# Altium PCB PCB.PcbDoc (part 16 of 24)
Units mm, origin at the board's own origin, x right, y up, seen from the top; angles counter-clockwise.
Board outline 100 x 160 mm, 10 copper layers (TOP_L1, L2, L3, L4, L5, L6, L7, L8, L9, BOTTOM_L10), stack 1.946 mm thick; 1358 components, 1149 nets, 6777 pads, 10914 vias.
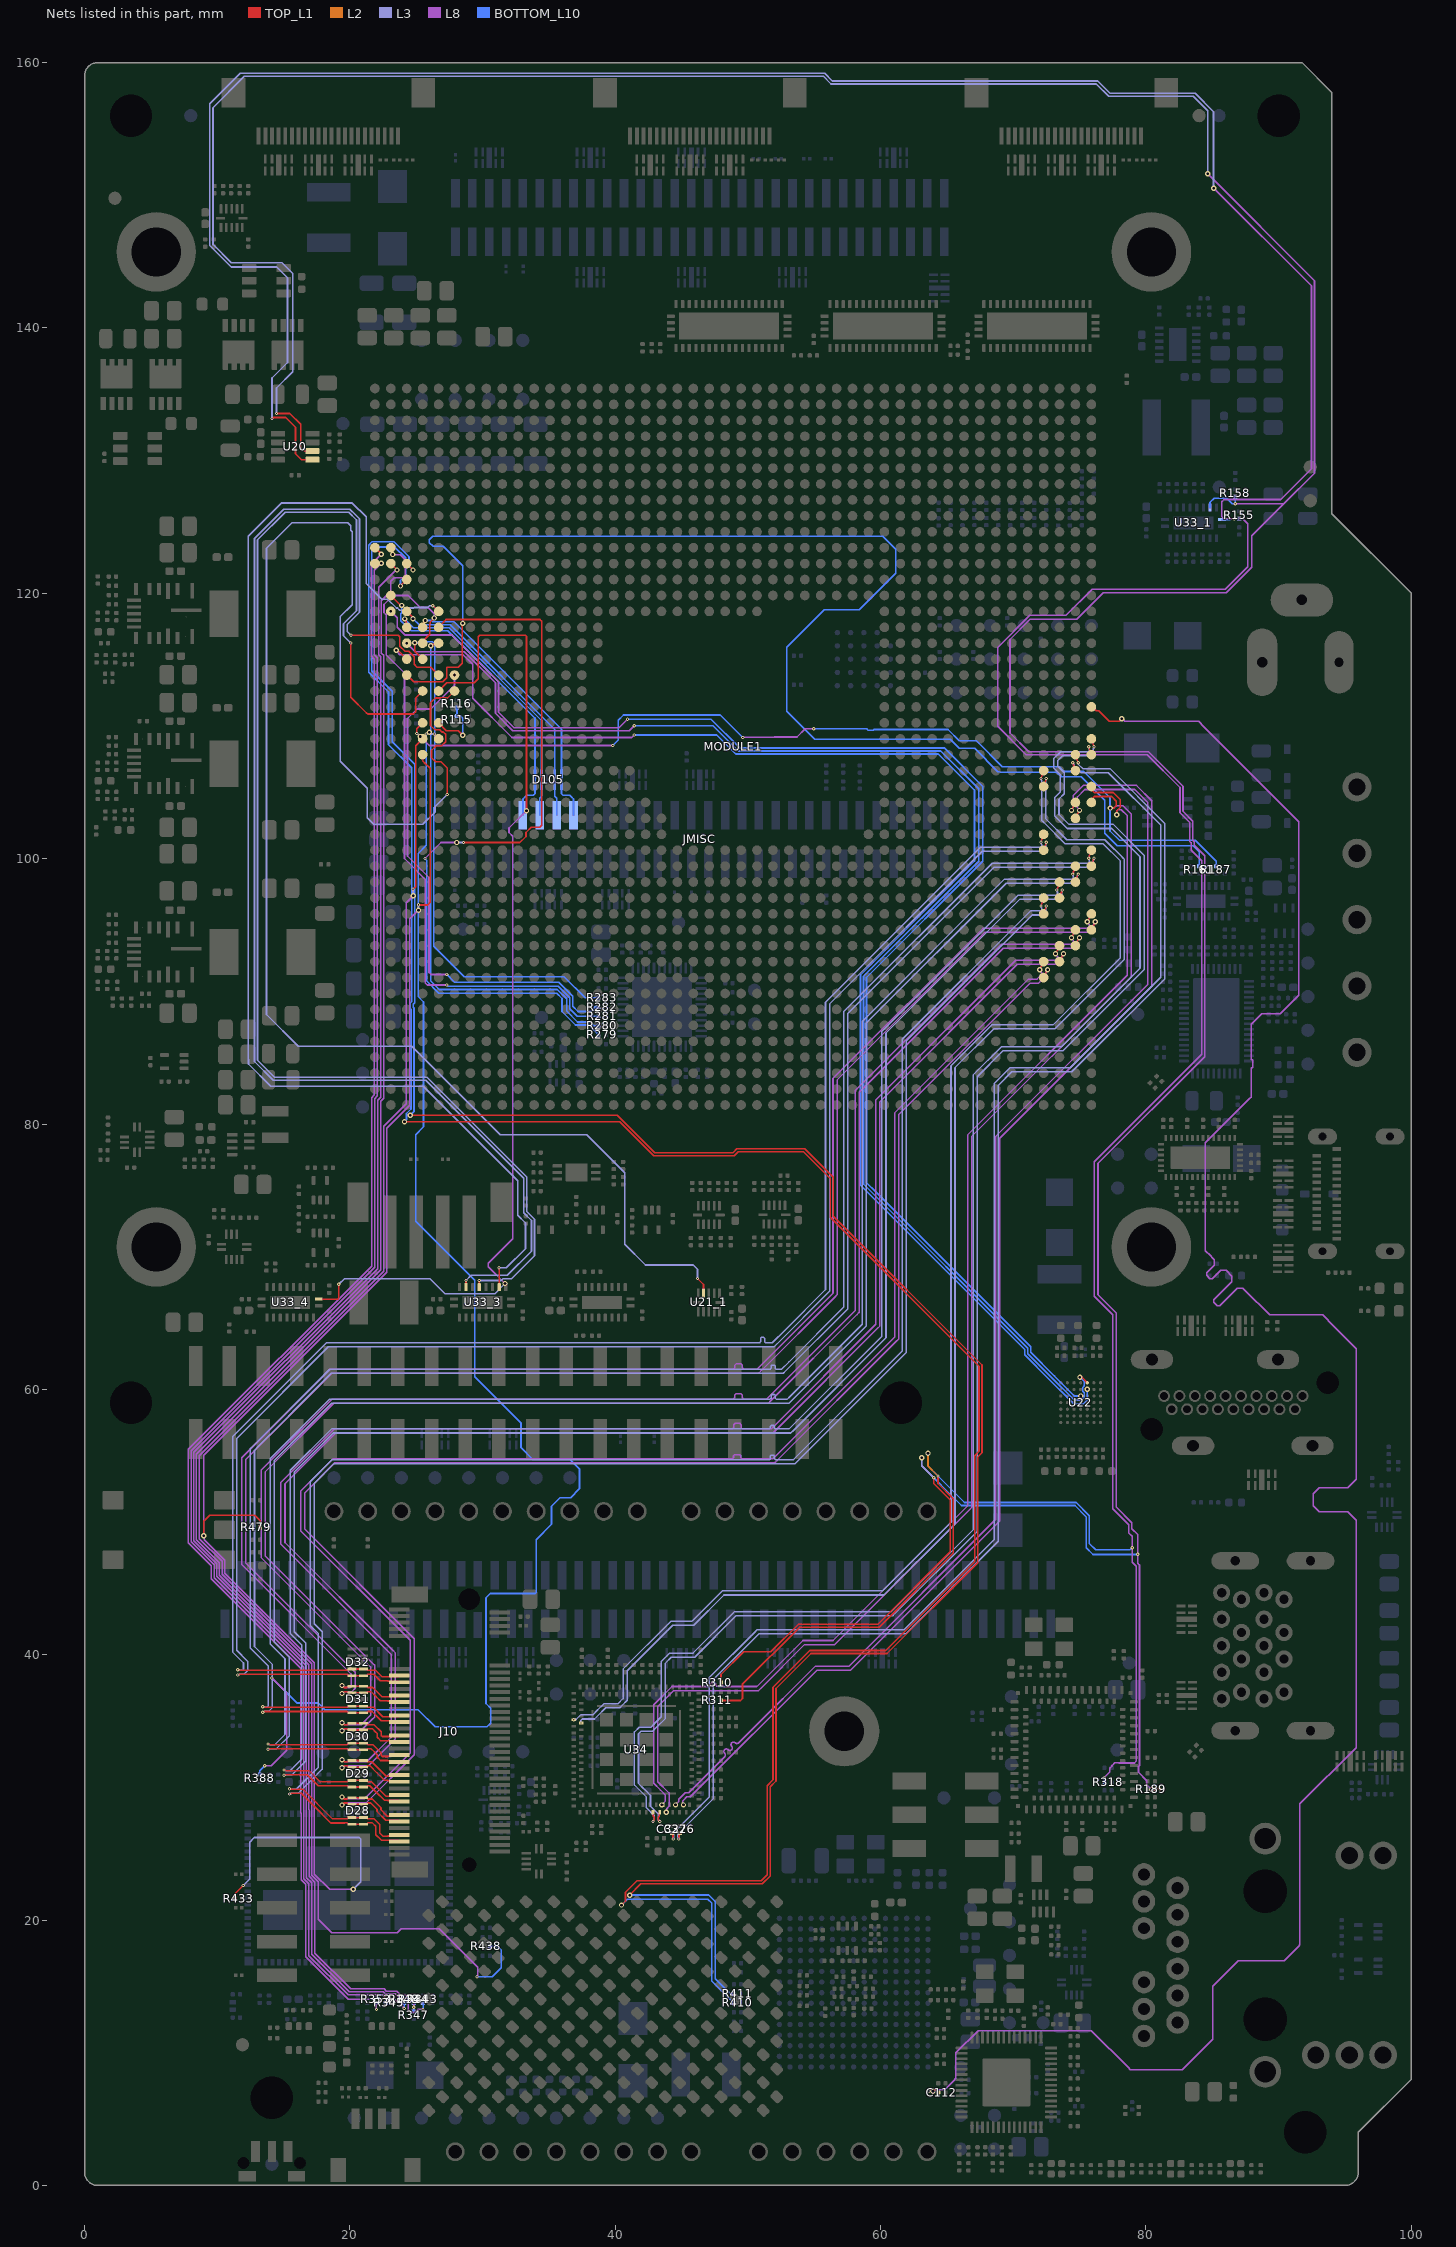
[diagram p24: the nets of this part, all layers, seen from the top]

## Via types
v1: diameter 0.25, hole 0.1, TOP_L1 to L2, tented both sides, 3439 vias
v2: diameter 0.25, hole 0.1, L2 to L3, tented both sides, 2256 vias
v3: diameter 0.25, hole 0.1, L9 to BOTTOM_L10, tented both sides, 1685 vias
v4: diameter 0.25, hole 0.1, L8 to L9, tented both sides, 1675 vias
v5: diameter 0.4, hole 0.2, L3 to L8, tented both sides, 1251 vias
v6: diameter 0.6, hole 0.3, TOP_L1 to BOTTOM_L10, tented both sides, 600 vias
v7: diameter 0.24, hole 0.1, TOP_L1 to L2, tented both sides, 8 vias

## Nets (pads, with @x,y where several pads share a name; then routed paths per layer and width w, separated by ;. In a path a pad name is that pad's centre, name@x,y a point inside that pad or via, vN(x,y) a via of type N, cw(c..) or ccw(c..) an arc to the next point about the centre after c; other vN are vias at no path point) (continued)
MD_GPIO_94_1: MODULE1.C28 R161.1 | length 107.1
  TOP_L1 w0.1: MODULE1.C28@24.282,113.836 24.797,113.321 26.895,113.321 26.909,113.335 26.982,113.335 27.282,113.635 27.282,114.376 27.341,114.435 28.182,114.435 28.482,114.735 28.482,117.702 v5(28.509,117.729)
  BOTTOM_L10 w0.1: v5(28.509,117.729) 28.509,122.074 27.048,123.535 26.261,123.535 25.982,123.814 25.982,124.029 26.26,124.306 60.177,124.306 61.149,123.335 61.149,121.516 58.401,118.768 55.749,118.768 52.914,115.933 52.914,111.109 55.037,108.986 65.237,108.986 65.915,108.308 67.082,108.308 68.83,106.561 68.954,106.561 69.004,106.511 73.29,106.511 73.643,106.158 75.136,106.158 76.876,104.418 76.876,101.918 77.829,100.965 83.547,100.965 84.003,100.509 R161.1@84.003,99.424
  other v1: 28.509,117.729
  other v2: 28.509,117.729
  other v3: 28.509,117.729
  other v4: 28.509,117.729
MD_GPIO_95_1: MODULE1.C35 R410.2 | length 179.3
  TOP_L1 w0.127: v4(24.113,80.163) 40.337,80.163 42.886,77.613 48.965,77.613 49.255,77.904 54.19,77.904 56.204,75.89 56.204,73.166 56.204,72.959 67.416,61.747 67.416,55.325 67.088,54.998 67.088,47.028 60.378,40.318 54.658,40.318 51.884,37.544 51.884,30.571 51.448,30.135 51.448,23.416 50.989,22.956 41.637,22.956 40.768,22.087 40.768,21.433 v5(40.463,21.129) ; MODULE1.C35@24.282,122.236 24.75,121.768 v1(24.75,121.75)
  BOTTOM_L10 w0.127: v4(24.113,80.163) 24.113,80.177 24.265,80.329 24.265,80.787 24.608,81.13 24.608,88.638 24.546,88.7 24.546,89.127 24.655,89.235 24.655,106.853 22.912,108.596 22.912,112.563 21.42,114.055 21.42,123.631 21.664,123.875 23.316,123.875 24.446,122.744 24.446,122.054 v1(24.75,121.75) ; v5(40.463,21.129) 40.907,21.572 46.973,21.572 47.258,21.287 47.258,15.41 R410.2@48.92,13.749
  other v1: 40.463,21.129 24.113,80.163
  other v2: 40.463,21.129 24.113,80.163 24.75,121.75
  other v3: 40.463,21.129 24.113,80.163 24.75,121.75
  other v4: 40.463,21.129 24.75,121.75
  other v5: 24.113,80.163 24.75,121.75
MD_GPIO_96_1: MODULE1.C34 R411.2 | length 176.9
  TOP_L1 w0.127: v5(23.814,120.55) 23.814,120.568 MODULE1.C34@24.282,121.036 ; v1(24.554,80.667) 40.153,80.667 42.98,77.84 48.871,77.84 49.161,78.131 54.284,78.131 56.431,75.984 56.431,73.26 56.431,73.053 67.643,61.841 67.643,55.231 67.315,54.904 67.315,46.93 60.476,40.091 54.752,40.091 52.111,37.45 52.111,30.477 51.675,30.041 51.675,23.322 51.083,22.729 41.925,22.729 41.089,21.894 v3(41.089,21.875)
  BOTTOM_L10 w0.127: v5(23.814,120.55) 23.814,120.968 24.202,121.356 24.202,122.667 23.387,123.482 21.828,123.482 21.647,123.301 21.647,114.149 23.185,112.611 23.185,108.823 24.882,107.126 24.882,89.141 24.773,89.033 24.773,88.794 24.835,88.732 24.835,80.949 v1(24.554,80.667) ; v3(41.089,21.875) 41.099,21.884 47.046,21.884 47.53,21.399 47.53,15.572 48.654,14.449 R411.2@48.891,14.449
  other v1: 41.089,21.875 23.814,120.55
  other v2: 41.089,21.875 24.554,80.667 23.814,120.55
  other v3: 24.554,80.667 23.814,120.55
  other v4: 41.089,21.875 24.554,80.667 23.814,120.55
  other v5: 41.089,21.875 24.554,80.667
MD_GPIO_99_2: MODULE1.E25 R115.2 R116.2 | length 4.7
  TOP_L1 w0.127: MODULE1.E25@26.682,110.236 26.682,110.219 27.252,109.649 28.158,109.649 v4(28.503,109.304)
  BOTTOM_L10 w0.127: R116.2@28.069,111.399 R115.2@28.069,110.749 28.346,110.749 28.503,110.592 v4(28.503,109.304)
  other v1: 28.503,109.304
  other v2: 28.503,109.304
  other v3: 28.503,109.304
  other v5: 28.503,109.304
MD_GPIO_100_1: MODULE1.E24 R388.1 | length 115.8
  TOP_L1 w0.127: v2(26.348,109.398) 26.348,109.37 MODULE1.E24@26.682,109.036
  L3 w0.127: v5(25.99,109.516) 26.108,109.398 v2(26.348,109.398)
  L8 w0.1: v4(13.575,31.625) 14.084,31.625 15.252,32.792 15.252,37.115 v4(14.117,38.249)
  L8 w0.127: v4(25.754,109.4) 25.9,109.547 25.959,109.547 v5(25.99,109.516)
  BOTTOM_L10 w0.1: R388.1@13.2,30.96 13.2,31.25 v4(13.575,31.625)
  BOTTOM_L10 w0.127: v4(14.117,38.249) 16,36.367 17.591,36.367 18.109,35.849 25.135,35.849 26.425,34.559 30.331,34.559 30.616,34.844 30.616,35.959 30.25,36.325 30.25,44.287 30.58,44.616 33.976,44.616 34.05,44.691 34.05,48.676 35.196,49.821 35.196,51.197 35.834,51.835 36.631,51.835 37.296,52.5 37.296,54.006 36.601,54.7 33.8,54.7 32.9,55.6 32.9,57.449 29.4,60.949 29.4,68.223 24.95,72.673 24.95,79.2 25.55,79.8 25.55,89.2 25.14,89.61 25.14,100.39 25.754,101.004 v4(25.754,109.4)
  other v1: 26.348,109.398
  other v3: 13.575,31.625 14.117,38.249 25.754,109.4
MD_GPIO_101_1: MODULE1.D24 R438.1 | length 118.6
  TOP_L1 w0.127: v2(24.752,97.689) 24.954,97.89 24.954,108.508 MODULE1.D24@25.482,109.036
  L3 w0.127: v2(24.752,97.689) 24.757,97.684 24.757,97.218 v5(24.762,97.213)
  L8 w0.1: v5(24.762,97.213) 24.233,96.685 24.233,81.533 22.541,79.841 22.541,68.915 8.631,55.005 8.631,48.756 10.359,47.028 10.359,46.063 17.105,39.317 17.105,28.414 17.124,28.395 17.124,23.373 17.596,22.901 17.596,20.079 18.622,19.053 23.56,19.053 23.854,19.348 26.729,19.348 29.635,16.443 29.635,15.796 v3(29.573,15.734)
  BOTTOM_L10 w0.127: v3(29.573,15.734) 30.724,15.734 31.4,16.41 31.4,17.749 31.139,18.01 R438.1@30.55,18.01
  other v1: 24.752,97.689
  other v4: 29.573,15.734
MD_GPIO_103_1: MODULE1.D23 R433.2 R479.2 | length 122.4
  TOP_L1 w0.127: v1(8.981,48.962) 8.981,50.048 9.436,50.503 12.832,50.503 13.232,50.103 R479.2@13.232,49.597 ; R433.2@11.335,21.621 11.333,21.623 11.333,21.981 v1(11.958,22.607) ; v2(25.162,96.513) 25.167,96.508 25.856,96.508 26.062,96.713 26.062,106.804 25.701,107.165 25.681,107.165 25.482,107.364 MODULE1.D23@25.482,107.836
  L3 w0.127: v1(11.958,22.607) 12.45,23.099 12.45,25.875 12.795,26.22 20.698,26.22 20.81,26.108 20.81,22.877 v5(20.252,22.319) ; v5(25.162,96.113) v2(25.162,96.513)
  L8 w0.1: v1(8.981,48.962) 9.008,48.935 9.008,48.662 10.559,47.111 10.559,46.146 17.313,39.392 17.313,28.489 17.324,28.478 17.324,23.456 18.46,22.319 v5(20.252,22.319) ; v5@8.981,49.001 8.981,55.034 22.768,68.821 22.768,79.678 24.516,81.426 24.516,95.467 v5(25.162,96.113)
  other v1: 25.162,96.513
  other v2: 11.958,22.607 8.981,48.962
  other v5: 8.981,48.962
MD_GPIO_104_1: MODULE1.D25 R187.1 | length 70.4
  TOP_L1 w0.127: v2(25.04,109.427) 25.04,109.794 MODULE1.D25@25.482,110.236
  L3 w0.127: v2(25.04,109.427) 25.056,109.427 25.281,109.202 v5(25.298,109.202)
  L8 w0.127: v5(25.298,109.202) 25.97,108.529 v4(39.809,108.529) ; v4(49.609,109.129) 49.618,109.138 51.953,109.138 51.986,109.171 53.698,109.171 54.307,109.78 v4(54.961,109.78)
  BOTTOM_L10 w0.127: v4(39.809,108.529) 40.227,108.947 40.227,110.435 40.621,110.829 47.909,110.829 v4(49.609,109.129) ; v4(54.961,109.78) 58.943,109.78 59.05,109.673 59.434,109.673 59.491,109.729 65.078,109.729 65.932,108.876 67.224,108.876 69.175,106.925 73.461,106.925 73.815,106.571 75.308,106.571 77.29,104.59 77.29,102.09 78.001,101.378 83.718,101.378 85.303,99.793 R187.1@85.303,99.424
  other v1: 25.04,109.427
  other v3: 39.809,108.529 49.609,109.129 54.961,109.78
MD_GPIO_105_1: MODULE1.E28 U33_3.8 | length 102.5
  TOP_L1 w0.127: v1(20.082,116.836) 23.642,116.836 23.754,116.724 23.754,116.017 24.15,115.621 24.445,115.621 24.841,115.225 24.841,114.652 25.056,114.436 26.082,114.436 MODULE1.E28@26.682,113.836 ; U33_3.8@28.75,67.7 v1(28.75,68.208)
  L3 w0.127: v1(20.082,116.836) 19.794,117.125 19.794,117.652 20.457,118.316 20.72,118.579 20.72,125.617 20.457,125.88 19.993,126.345 19.31,126.345 15.022,126.345 12.8,124.122 12.8,86.871 12.8,86.292 12.8,85.685 12.8,85.051 12.805,85.047 12.805,84.714 14.217,83.302 25.709,83.302 33.105,75.907 33.105,73.306 33.684,72.727 33.684,70.421 31.861,68.599 29.141,68.599 v1(28.75,68.208)
  other v2: 28.75,68.208 20.082,116.836
MD_GPIO_106_1: MODULE1.D27 U33_3.6 | length 104.6
  TOP_L1 w0.127: v2(20.069,116.249) 20.069,112.168 21.254,110.983 21.271,110.983 21.347,110.908 24.797,110.908 24.954,111.065 24.954,112.108 MODULE1.D27@25.482,112.636 ; U33_3.6@29.75,67.7 v2(29.75,68.208)
  L3 w0.127: v2(20.069,116.249) 19.52,116.798 19.52,117.699 20.493,118.673 20.493,125.523 19.899,126.118 15.117,126.118 13.027,124.028 13.027,85.145 13.032,85.141 13.032,84.808 14.311,83.529 25.803,83.529 33.332,76.001 33.332,73.4 33.911,72.821 33.911,70.069 32.18,68.339 31.54,68.339 31.409,68.208 v2(29.75,68.208)
  other v1: 29.75,68.208 20.069,116.249
MD_GPIO_107_1: MODULE1.E32 U33_3.3 | length 95.1
  TOP_L1 w0.127: v2(26.25,119.05) 26.259,119.05 26.673,118.636 MODULE1.E32@26.682,118.636 ; v2(31.241,69.17) 31.246,69.165 31.246,67.704 U33_3.3@31.25,67.7
  L3 w0.127: v2(26.25,119.05) 25.991,119.05 25.867,118.925 24.858,118.925 24.82,118.887 24.215,118.887 24.051,118.723 23.75,118.723 23.586,118.887 23.505,118.887 22.83,119.561 22.398,119.561 21.219,120.74 21.219,125.76 20.181,126.799 14.834,126.799 12.346,124.311 12.346,86.649 12.346,86.104 12.346,85.497 12.346,84.863 12.351,84.858 12.351,84.526 14.029,82.848 25.521,82.848 32.651,75.718 32.651,73.118 33.23,72.539 33.23,70.609 31.781,69.161 31.25,69.161 v2(31.241,69.17)
  other v1: 31.241,69.17 26.25,119.05
MD_GPIO_108_1: MODULE1.F27 U21_1.4 | length 129.9
  TOP_L1 w0.127: v2(27.34,104.84) 27.34,106.833 26.866,107.308 26.463,107.308 26.154,107.617 26.154,108.154 26.508,108.508 26.901,108.508 27.211,108.817 27.211,109.369 27.04,109.54 26.926,109.54 26.758,109.708 26.41,109.708 26.078,110.04 26.078,111.741 26.288,111.952 26.444,112.108 27.354,112.108 MODULE1.F27@27.882,112.636 ; v2(46.202,68.356) 46.65,67.908 U21_1.4@46.65,67.25
  L3 w0.127: v2(27.34,104.84) 26.406,103.906 26.406,103.497 25.495,102.586 21.789,102.586 21.302,103.073 21.302,105.301 19.269,107.334 19.269,118.249 20.169,119.149 20.169,124.649 20.056,124.763 20.056,125.084 19.829,125.31 15.635,125.31 13.708,123.383 13.708,88.258 16.102,85.865 24.652,85.865 31.331,79.185 37.855,79.185 38.105,78.936 40.71,76.331 40.71,70.943 42.278,69.374 45.884,69.374 46.202,69.056 v2(46.202,68.356)
  other v1: 46.202,68.356 27.34,104.84
MD_GPIO_109_1: MODULE1.E27 U33_4.1 | length 77.1
  TOP_L1 w0.127: U33_4.1@17.65,66.8 19.075,66.8 19.162,66.887 v1(19.162,67.913) ; MODULE1.E27@26.682,112.636 27.295,113.249 29.369,113.249 29.669,113.549 29.669,116.734 29.781,116.846 33.212,116.846 33.302,116.756 v5(33.302,103.621)
  L3 w0.127: v1(19.162,67.913) 19.592,68.343 26.032,68.343 27.162,67.213 30.929,67.213 v5(31.691,67.975)
  L8 w0.127: v5(31.691,67.975) 30.434,69.231 30.434,69.5 32.276,71.341 32.276,101.677 31.987,101.966 31.987,102.306 v5(33.302,103.621)
  other v1: 33.302,103.621
  other v2: 19.162,67.913 33.302,103.621
MD_LPASS_GPIO_110: MODULE1.F28 R282.1 | length 39.8
  L8 w0.127: v4(27.286,91.275) 26.113,91.275 25.964,91.424 25.964,98.574 24.334,100.204 24.334,110.561 25.052,111.279 26.09,111.279 27.882,113.07 v2(27.882,113.836)
  BOTTOM_L10 w0.127: v4(27.286,91.275) 27.886,90.675 35.732,90.675 36.786,89.62 36.786,88.875 37.186,88.475 38.186,88.475 38.428,88.716 38.428,88.816 R282.1@38.748,88.816
  other v1: 27.882,113.836
  other v3: 27.286,91.275
  other v4: 27.882,113.836
  other v5: 27.882,113.836
MD_LPASS_GPIO_111: MODULE1.D30 R281.1 | length 51.6
  TOP_L1 w0.127: MODULE1.D30@25.482,116.236 25.482,116.395 26.011,116.923 26.011,117.69 26.053,117.733 26.053,117.837 v5(26.359,118.142)
  L8 w0.127: v5(26.359,118.142) 26.359,118.454 25.877,118.935 25.284,118.935 24.385,119.835 23.255,119.835 22.571,119.151 22.571,118.549 22.743,118.377 22.743,116.98 22.743,116.257 22.743,115.351 24.107,113.987 24.107,100.005 25.683,98.43 25.683,90.624 25.831,90.475 v4(27.286,90.475)
  BOTTOM_L10 w0.127: v4(27.286,90.475) 27.386,90.375 35.711,90.375 36.559,89.526 36.559,88.684 37.127,88.116 R281.1@38.748,88.116
  other v1: 26.359,118.142
  other v2: 26.359,118.142
  other v3: 27.286,90.475
MD_LPASS_GPIO_112: MODULE1.E30 R280.1 | length 40.5
  TOP_L1 w0.127: v1(26.102,116.054) 26.135,116.054 26.217,116.136 26.582,116.136 MODULE1.E30@26.682,116.236
  BOTTOM_L10 w0.127: 26.101,114.404 26.101,90.78 26.743,90.138 35.626,90.138 36.332,89.432 36.332,88.511 37.157,87.687 38.098,87.687 38.369,87.416 R280.1@38.748,87.416 ; 26.102,114.405 v1(26.102,116.054)
  other v2: 26.102,116.054
  other v3: 26.102,116.054
  other v4: 26.102,116.054
  other v5: 26.102,116.054
MD_LPASS_GPIO_113: MODULE1.E31 R279.1 | length 58
  TOP_L1 w0.127: MODULE1.E31@26.682,117.436 27.04,117.794 27.04,117.814 27.244,118.018 34.323,118.018 34.452,117.888 34.452,102.513 34.303,102.365 33.663,102.365 33.265,101.966 33.265,101.671 32.807,101.213 v2(28.562,101.213)
  L3 w0.127: v5(28.062,101.213) v2(28.562,101.213)
  L8 w0.127: v3(25.662,100.013) 26.862,101.213 v5(28.062,101.213)
  BOTTOM_L10 w0.127: v3(25.662,100.013) 25.662,99.98 25.782,99.86 25.782,90.779 26.696,89.864 35.58,89.864 35.987,89.457 35.987,88.478 37.005,87.46 38.004,87.46 R279.1@38.748,86.716
  other v1: 28.562,101.213
  other v4: 25.662,100.013
MD_LPASS_GPIO_115: MODULE1.D29 R283.1 | length 39.9
  TOP_L1 w0.127: v2(24.894,116.281) 24.894,115.624 MODULE1.D29@25.482,115.036
  BOTTOM_L10 w0.127: v2(24.894,116.281) 25.575,116.281 25.637,116.342 26.221,116.342 26.39,116.173 26.39,103.894 26.328,103.832 26.328,93.388 28.609,91.107 36.139,91.107 37.73,89.516 R283.1@38.748,89.516
  other v1: 24.894,116.281
  other v3: 24.894,116.281
  other v4: 24.894,116.281
  other v5: 24.894,116.281
MD_LPASS_GPIO_120: D105.1 D105.10 JMISC.46 MODULE1.D31 | length 21.4
  TOP_L1 w0.127: MODULE1.D31@25.482,117.436 25.597,117.551 25.597,117.827 25.682,117.912 v1(25.682,117.945)
  BOTTOM_L10 w0.127: v1(25.682,117.945) 26.148,117.945 26.243,117.85 27.849,117.85 35.944,109.755 35.944,104.898 36.064,104.778 36.564,104.778 36.727,104.615 36.732,104.615 36.849,104.498 JMISC.46@36.849,103.278
  other v2: 25.682,117.945
  other v3: 25.682,117.945
  other v4: 25.682,117.945
  other v5: 25.682,117.945
MD_LPASS_GPIO_121: D105.2 D105.9 JMISC.48 MODULE1.C32 | length 21.4
  TOP_L1 w0.127: MODULE1.C32@24.282,118.636 24.726,118.192 24.726,118.109 v1(24.75,118.085)
  BOTTOM_L10 w0.127: v1(24.75,118.085) 25.212,117.623 27.557,117.623 35.444,109.736 D105.9@35.444,106.391 D105.2@35.444,105.516 35.444,104.698 35.579,104.563 JMISC.48@35.579,103.278
  other v2: 24.75,118.085
  other v3: 24.75,118.085
  other v4: 24.75,118.085
  other v5: 24.75,118.085
MD_LPASS_GPIO_122: D105.4 D105.7 JMISC.50 MODULE1.C31 | length 21.4
  TOP_L1 w0.127: v1(24.122,118.068) 24.122,118.035 24.256,117.901 24.256,117.462 MODULE1.C31@24.282,117.436
  BOTTOM_L10 w0.127: v1(24.122,118.068) 24.794,117.396 27.463,117.396 34.444,110.415 D105.7@34.444,106.391 34.444,104.698 34.309,104.563 JMISC.50@34.309,103.278
  other v2: 24.122,118.068
  other v3: 24.122,118.068
  other v4: 24.122,118.068
  other v5: 24.122,118.068
MD_LPASS_GPIO_123: D105.5 D105.6 JMISC.52 MODULE1.B33 | length 23.4
  TOP_L1 w0.127: MODULE1.B33@23.082,119.836 23.808,119.11 23.877,119.11 v1(23.901,119.086)
  BOTTOM_L10 w0.127: v1(23.901,119.086) 23.901,118.528 23.833,118.461 23.833,117.936 23.984,117.785 23.996,117.785 24.612,117.169 27.369,117.169 33.944,110.594 D105.5@33.944,105.516 33.944,104.898 33.824,104.778 33.324,104.778 33.162,104.615 33.157,104.615 33.039,104.498 JMISC.52@33.039,103.278
  other v2: 23.901,119.086
  other v3: 23.901,119.086
  other v4: 23.901,119.086
  other v5: 23.901,119.086
MD_LPASS_GPIO_125: MODULE1.C29 U22.C2 | length 109.1
  TOP_L1 w0.127: v1(23.5,115.7) 23.618,115.7 MODULE1.C29@24.282,115.036
  L8 w0.127: v1(23.5,115.7) 23.5,115.632 23.598,115.534 23.76,115.372 28.527,115.372 29.252,114.647 29.252,112.094 32.214,109.132 41.238,109.132 v3(41.423,109.316)
  BOTTOM_L10 w0.127: v3(41.423,109.316) 47.65,109.316 49.074,107.892 64.354,107.892 67.078,105.167 67.078,99.823 58.482,91.226 58.482,75.387 70.862,63.007 70.862,62.597 72.676,60.783 74.551,58.908 75.29,58.908 75.575,59.193 v3(75.575,60)
  other v1: 75.575,60
  other v2: 75.575,60 23.5,115.7
  other v4: 75.575,60 41.423,109.316
  other v5: 75.575,60 23.5,115.7
MD_LPASS_GPIO_126: MODULE1.B32 U22.D3 | length 108.9
  L8 w0.127: v1(23.082,118.636) 23.57,118.148 23.57,117.45 24.17,116.85 27.691,116.85 31.197,113.344 31.197,111.044 32.364,109.877 40.284,109.877 v4(40.923,110.516)
  BOTTOM_L10 w0.127: v4(40.923,110.516) 47.217,110.516 49.387,108.346 64.79,108.346 67.695,105.441 67.695,99.797 58.936,91.038 58.936,75.58 59.662,74.854 71.316,63.2 71.316,62.785 73.101,61 74.601,59.5 v2(75.075,59.5)
  other v1: 75.075,59.5
  other v2: 23.082,118.636
  other v3: 75.075,59.5 40.923,110.516
  other v4: 75.075,59.5
  other v5: 75.075,59.5 23.082,118.636
MD_LPASS_GPIO_127: MODULE1.C30 U22.C1 | length 108.9
  TOP_L1 w0.127: v2(75.02,60.916) 75.043,60.892 75.183,60.892 U22.C1@75.575,60.5
  L8 w0.127: v1(24.282,116.236) 24.919,115.599 28.621,115.599 30.97,113.25 30.97,110.95 32.27,109.65 41.057,109.65 v4(41.423,110.016)
  BOTTOM_L10 w0.127: v4(41.423,110.016) 47.364,110.016 49.261,108.119 64.541,108.119 67.393,105.268 67.393,99.816 58.709,91.132 58.709,75.481 71.089,63.101 71.089,62.691 72.78,61 74.584,59.196 75.156,59.196 75.347,59.387 75.347,59.736 75.228,59.856 75.228,60.144 75.347,60.264 75.347,60.588 v2(75.02,60.916)
  other v1: 75.02,60.916
  other v2: 24.282,116.236
  other v3: 75.02,60.916 41.423,110.016
  other v4: 75.02,60.916
  other v5: 75.02,60.916 24.282,116.236
MD_LPASS_GPIO_129: MODULE1.A36 R353.1 | length 124.1
  TOP_L1 w0.127: MODULE1.A36@21.882,123.436 22.35,122.968 v2(22.35,122.95)
  L8 w0.1: v4(22.005,13.259) 22,13.264 22,13.76 21.725,14.035 19.862,14.035 16.674,17.224 16.674,22.692 16.324,23.042 16.324,28.064 16.305,28.083 16.305,38.986 9.559,45.731 9.559,46.697 7.831,48.424 7.831,55.489 21.633,69.291 21.633,81.993 21.85,82.21 21.85,115.033 21.606,115.278 21.606,122.206 v2(22.35,122.95)
  BOTTOM_L10 w0.1: R353.1@22,13.76 22,13.264 v4(22.005,13.259)
  other v1: 22.35,122.95
  other v3: 22.005,13.259
  other v5: 22.35,122.95
MD_LPASS_GPIO_130: MODULE1.B35 R343.1 | length 126.5
  TOP_L1 w0.127: MODULE1.B35@23.082,122.236 23.55,121.768 v2(23.55,121.75)
  L8 w0.1: v2(23.55,121.75) 23.436,121.75 22.157,120.472 22.157,115.368 22.304,115.221 22.304,82.022 22.087,81.804 22.087,69.103 8.231,55.247 8.231,48.59 9.959,46.862 9.959,45.897 16.705,39.151 16.705,28.249 16.724,28.23 16.724,23.207 17.128,22.803 17.128,17.412 19.956,14.583 22.513,14.583 22.653,14.443 23.433,14.443 23.755,14.12 24.348,14.12 24.407,14.062 24.407,13.203 24.572,13.038 24.91,13.038 25.132,13.26 v3(25.511,13.26)
  BOTTOM_L10 w0.1: R343.1@25.5,13.76 25.511,13.749 v3(25.511,13.26)
  other v1: 23.55,121.75
  other v4: 25.511,13.26
  other v5: 23.55,121.75
MD_LPASS_GPIO_131: MODULE1.B36 R344.1 R347.1 | length 127.7
  TOP_L1 w0.127: MODULE1.B36@23.082,123.436 23.196,123.322 23.196,122.944 v1(23.22,122.921)
  L8 w0.1: v1(23.22,122.921) 23.788,122.921 24.17,122.539 24.17,121.324 24.008,121.162 23.338,121.162 23.091,120.915 23.091,120.171 22.357,119.437 22.357,115.489 22.531,115.315 22.531,81.928 22.314,81.71 22.314,69.009 8.431,55.126 8.431,48.673 10.159,46.945 10.159,45.98 16.905,39.234 16.905,28.332 16.924,28.313 16.924,23.29 17.355,22.859 17.355,17.506 20.051,14.81 22.568,14.81 22.736,14.643 23.525,14.643 23.847,14.32 24.636,14.32 24.803,14.153 v4(24.803,13.436)
  BOTTOM_L10 w0.127: R347.1@24.8,13.11 R344.1@24.8,13.76
  other v2: 23.22,122.921
  other v3: 24.803,13.436
  other v5: 23.22,122.921
MD_LPASS_GPIO_132: MODULE1.A35 R345.1 R348.1 | length 124.9
  TOP_L1 w0.127: MODULE1.A35@21.882,122.236 21.912,122.266 v2(22.35,122.266)
  L8 w0.1: v2(22.35,122.266) 21.825,121.74 21.825,115.38 22.077,115.127 22.077,82.116 21.86,81.899 21.86,69.197 8.031,55.368 8.031,48.507 9.759,46.78 9.759,45.814 16.505,39.068 16.505,28.166 16.524,28.147 16.524,23.125 16.901,22.747 16.901,17.318 19.862,14.356 22.457,14.356 v3(22.691,14.122) 23.304,14.122 v3(24.085,13.341)
  BOTTOM_L10 w0.1: v3(22.691,14.122) 22.7,14.113 R345.1@22.7,13.76 ; v3(24.085,13.341) 24.1,13.356 R348.1@24.1,13.76
  other v1: 22.35,122.266
  other v4: 24.085,13.341 22.691,14.122
  other v5: 22.35,122.266
MD_PCIE0_2LANES.REFCLK_1_N: MODULE1.BC21 U34.AF34 | length 104.8
  TOP_L1 w0.122: MODULE1.BC21@72.282,105.436 72.43,105.88 v1(72.482,106.036)
  L3 w0.117: v1(37.421,34.849) 37.409,34.862 37.409,35.053 37.512,35.156 38.436,35.156 38.615,35.335 39.28,36 40.329,36 40.508,36.178 40.895,36.565 40.895,38.788 44.33,42.223 45.909,42.223 48.187,44.501 60.249,44.501 60.428,44.68 65.427,49.679 65.606,49.858 65.606,62.055 65.606,72.32 65.606,84.256 68.536,87.186 73.151,87.186 78.376,92.411 78.376,99.942 78.287,100.031 78.108,100.21 77.198,101.12 76.974,101.344 76.885,101.433 74.031,101.433 72.434,103.029 72.434,105.901 72.457,105.923 72.457,106.011 v1(72.482,106.036)
  other v2: 37.421,34.849 72.482,106.036
MD_PCIE0_2LANES.REFCLK_1_P: MODULE1.BC22 U34.AG35 | length 104.8
  TOP_L1 w0.122: v2(72.082,106.036) 72.134,106.192 MODULE1.BC22@72.282,106.636
  L3 w0.117: v1(36.871,35.099) 36.891,35.118 37.043,35.118 37.386,35.461 38.31,35.461 38.453,35.604 38.494,35.645 38.485,35.654 38.927,36.096 38.936,36.087 39.148,36.299 39.153,36.304 40.203,36.304 40.59,36.692 40.59,38.914 44.204,42.528 45.783,42.528 48.06,44.806 60.123,44.806 65.301,49.984 65.301,62.055 65.301,72.32 65.301,84.382 68.41,87.491 73.025,87.491 78.071,92.538 78.071,99.816 76.759,101.128 73.904,101.128 72.308,102.724 72.219,102.814 72.13,102.903 72.13,105.901 72.108,105.923 72.108,106.011 v2(72.082,106.036)
  other v1: 72.082,106.036
  other v2: 36.871,35.099
MD_PCIE0_2LANES.RX0_1_N: C327.2 MODULE1.BE22 | length 110.5
  TOP_L1 w0.122: C327.2@44.275,26.552 44.349,26.478 44.349,26.137 v1(44.373,26.113) ; v1(74.482,107.236) 74.534,107.08 MODULE1.BE22@74.682,106.636
  L3 w0.117: v1(44.373,26.113) 44.399,26.138 44.399,26.233 44.421,26.255 44.421,26.614 47.088,29.281 47.088,38.281 50.503,41.696 50.682,41.875 61.757,41.875 68.551,48.669 68.551,83.036 69.756,84.241 74.283,84.241 81.106,91.064 81.106,102.528 77.153,106.481 75.099,106.481 74.603,106.977 74.603,107.079 74.482,107.2 v1(74.482,107.236)
  other v2: 44.373,26.113 74.482,107.236
MD_PCIE0_2LANES.RX0_1_P: C326.2 MODULE1.BE23 | length 110.5
  TOP_L1 w0.122: v1(44.773,26.113) 44.798,26.137 44.798,26.475 C326.2@44.875,26.552 ; MODULE1.BE23@74.682,107.836 74.83,107.392 v1(74.882,107.236)
  L3 w0.117: v1(44.773,26.113) 44.748,26.138 44.748,26.233 44.726,26.255 44.726,26.488 47.393,29.155 47.393,38.155 50.808,41.57 61.883,41.57 68.856,48.543 68.856,82.91 69.882,83.936 74.409,83.936 81.411,90.938 81.411,102.654 77.279,106.786 75.226,106.786 74.908,107.104 74.908,107.211 v1(74.882,107.236)
  other v2: 44.773,26.113 74.882,107.236
MD_PCIE0_2LANES.RX1_1_N: MODULE1.BF23 U34.A13 | length 117.3
  TOP_L1 w0.122: v1(42.841,27.429) 42.841,27.464 42.939,27.561 42.939,27.753 42.864,27.829 42.864,28.107 U34.A13@42.841,28.129 ; v1(75.682,108.436) 75.734,108.28 MODULE1.BF23@75.882,107.836
  L3 w0.117: v1(42.841,27.429) 42.841,27.465 42.939,27.563 42.939,27.867 42.35,28.456 42.35,29.269 41.445,30.174 41.445,34.174 41.812,34.541 42.688,34.541 43.019,34.872 43.473,35.326 43.473,39.497 44.097,40.121 45.861,40.121 48.813,43.072 48.992,43.251 60.814,43.251 66.968,49.404 66.968,83.692 69.1,85.824 73.627,85.824 79.549,91.746 79.549,100.138 77.416,102.271 74.064,102.271 73.136,103.198 73.136,104.62 73.526,105.009 73.526,106.354 73.215,106.664 73.036,106.843 73.036,107.52 73.574,108.058 75.661,108.058 75.73,108.126 75.73,108.301 75.708,108.323 75.708,108.411 v1(75.682,108.436)
  other v2: 42.841,27.429 75.682,108.436
MD_PCIE0_2LANES.RX1_1_P: MODULE1.BF24 U34.A11 | length 117.3
  TOP_L1 w0.122: v2(43.341,27.429) 43.341,27.464 43.244,27.561 43.244,27.753 43.319,27.829 43.319,28.107 U34.A11@43.341,28.129 ; MODULE1.BF24@75.882,109.036 76.03,108.592 v2(76.082,108.436)
  L3 w0.117: v2(43.341,27.429) 43.341,27.465 43.244,27.563 43.244,27.937 43.244,27.993 43.065,28.172 42.993,28.244 42.655,28.582 42.655,29.395 42.251,29.799 42.15,29.9 41.75,30.3 41.75,34.048 41.939,34.236 42.814,34.236 43.145,34.567 43.778,35.2 43.778,39.371 44.223,39.816 45.988,39.816 49.118,42.946 60.941,42.946 67.273,49.278 67.273,83.566 69.226,85.519 73.753,85.519 79.856,91.622 79.856,100.262 77.543,102.575 74.19,102.575 73.441,103.325 73.441,104.494 73.83,104.883 73.83,106.48 73.341,106.969 73.341,107.394 73.7,107.753 75.787,107.753 76.034,108 76.034,108.301 76.057,108.323 76.057,108.411 v2(76.082,108.436)
  other v1: 43.341,27.429 76.082,108.436
MD_PCIE0_2LANES.TX0_1_N: MODULE1.BE19 U34.B6 | length 100.5
  TOP_L1 w0.122: MODULE1.BE19@74.682,103.036 74.891,103.455 v2(74.982,103.636)
  L8 w0.117: v5(44.541,28.679) 44.79,28.928 44.79,29.112 45.268,29.59 45.53,29.59 48.208,32.268 48.249,32.309 ccw(c48.118,32.441) 48.249,32.572 48.239,32.582 cw(c48.37,32.713) 48.239,32.844 cw(c48.37,32.713) 48.501,32.844 48.511,32.834 ccw(c48.642,32.965) 48.773,32.834 ccw(c48.642,32.965) 48.773,33.096 cw(c48.905,33.227) 48.773,33.358 cw(c48.905,33.227) 49.036,33.358 ccw(c49.167,33.49) 49.298,33.358 50.36,34.42 54.971,39.031 55.06,39.121 57.59,39.121 68.675,50.206 68.675,79.06 68.853,79.238 80.125,90.51 80.125,104.241 79.156,105.21 75.392,105.21 74.834,104.653 74.834,103.846 74.982,103.698 v2(74.982,103.636)
  other v1: 44.591,28.679 74.982,103.636
  other v2: 44.591,28.679
  other v5: 74.982,103.636
MD_PCIE0_2LANES.TX0_1_P: MODULE1.BE20 U34.B4 | length 100.5
  TOP_L1 w0.122: v1(74.382,103.636) 74.473,103.818 MODULE1.BE20@74.682,104.236
  L8 w0.117: v5(45.141,28.679) 45.095,28.726 45.095,28.986 45.395,29.286 45.656,29.286 55.186,38.816 57.716,38.816 68.98,50.08 68.98,63.729 68.98,77.948 68.98,78.934 80.43,90.384 80.43,104.368 79.283,105.515 75.266,105.515 74.53,104.779 74.53,103.846 74.382,103.698 v1(74.382,103.636)
  other v1: 45.091,28.679
  other v2: 45.091,28.679 74.382,103.636
  other v5: 74.382,103.636
MD_PCIE0_2LANES.TX1_1_N: MODULE1.BF20 U34.A9 | length 100.7
  TOP_L1 w0.122: MODULE1.BF20@75.882,104.236 75.998,104.352 75.998,104.574 76.108,104.684 76.336,104.684 77.408,104.684 77.757,104.335 77.757,103.982 77.586,103.811 v1(77.306,103.811)
  L8 w0.117: v2(43.841,28.129) 43.87,28.158 43.87,28.397 44.054,28.581 44.054,29.577 43.2,30.431 43.2,36.1 44.4,37.3 50.8,37.3 50.979,37.479 54.266,40.766 56.535,40.766 56.713,40.944 66.677,50.908 66.856,51.087 66.856,62.457 66.856,78.242 66.856,79.049 78.889,91.082 78.889,103.374 78.267,103.996 77.771,103.996 77.595,103.82 77.315,103.82 v1(77.306,103.811)
  other v1: 43.841,28.129
  other v2: 77.306,103.811
  other v5: 43.841,28.129 77.306,103.811
MD_PCIE0_2LANES.TX1_1_P: MODULE1.BF21 U34.B10 | length 100.6
  TOP_L1 w0.122: MODULE1.BF21@75.882,105.436 75.998,105.32 75.998,105.098 76.108,104.988 76.209,104.988 77.535,104.988 78.062,104.461 78.062,103.856 77.801,103.595 v1(77.801,103.316)
  L3 w0.117: v5(43.491,28.679) v2(43.591,28.679)
  L8 w0.117: v5(43.491,28.679) 43.491,28.686 43.749,28.944 43.749,29.451 43.4,29.8 42.895,30.305 42.895,36.226 44.274,37.605 47.019,37.605 47.077,37.605 ccw(c47.077,37.735) 47.207,37.735 47.207,37.777 cw(c47.337,37.777) 47.337,37.907 47.448,37.907 cw(c47.448,37.777) 47.578,37.777 47.578,37.735 ccw(c47.708,37.735) 47.708,37.605 49.706,37.605 50.674,37.605 54.14,41.071 56.409,41.071 66.551,51.213 66.551,62.457 66.551,78.242 66.551,79.175 78.584,91.208 78.584,103.247 78.14,103.691 77.897,103.691 77.81,103.604 77.81,103.325 v1(77.801,103.316)
  other v1: 43.591,28.679
  other v2: 77.801,103.316
  other v5: 77.801,103.316
MD_PCIE1_4LANES.REFCLK_1_N: D32.1 D32.10 J10.53 MODULE1.BC17 | length 124.4
  TOP_L1 w0.122: v2(11.545,38.474) 11.569,38.499 11.657,38.499 11.68,38.522 13.838,38.522 19.806,38.522 19.904,38.425 D32.10@20.141,38.425 D32.1@21.016,38.425 21.254,38.425 21.351,38.522 21.793,38.522 22.05,38.265 22.288,38.027 22.846,38.027 22.859,38.014 23.637,38.014 J10.53@23.726,37.925 ; MODULE1.BC17@72.282,100.636 72.43,101.08 v2(72.482,101.236)
  L3 w0.117: v2(11.545,38.474) 11.57,38.5 11.658,38.5 11.68,38.522 12.024,38.522 12.284,38.782 12.284,39.509 11.46,40.333 11.46,56.301 18.368,63.209 51.965,63.209 52.144,63.388 56.149,67.393 56.149,89.046 67.656,100.553 72.187,100.553 72.434,100.8 72.434,101.101 72.457,101.123 72.457,101.211 v2(72.482,101.236)
  other v1: 11.545,38.474 72.482,101.236
MD_PCIE1_4LANES.REFCLK_1_P: D32.2 D32.9 J10.55 MODULE1.BC18 | length 124.5
  TOP_L1 w0.122: v2(11.545,38.874) 11.569,38.85 11.657,38.85 11.68,38.827 13.712,38.827 19.806,38.827 19.904,38.925 D32.9@20.015,38.925 ; D32.9@20.141,38.925 D32.2@21.016,38.925 21.254,38.925 21.351,38.827 21.919,38.827 22.415,38.331 22.854,38.331 22.859,38.336 23.637,38.336 J10.55@23.726,38.425 ; v2(72.082,101.236) 72.134,101.392 MODULE1.BC18@72.282,101.836
  L3 w0.117: v2(11.545,38.874) 11.57,38.849 11.658,38.849 11.68,38.827 11.898,38.827 11.979,38.908 11.979,39.383 11.155,40.207 11.155,56.427 18.242,63.514 50.825,63.514 50.884,63.514 50.952,63.582 50.952,63.854 51.012,63.914 51.193,63.914 51.253,63.854 51.253,63.582 51.322,63.514 51.839,63.514 52.784,64.459 55.844,67.519 55.844,89.172 67.53,100.858 72.061,100.858 72.13,100.926 72.13,101.101 72.108,101.123 72.108,101.211 v2(72.082,101.236)
  other v1: 11.545,38.874 72.082,101.236
MD_PCIE1_4LANES.RX0_1_N: D31.1 D31.10 J10.41 MODULE1.BF16 | length 127.2
  TOP_L1 w0.122: v1(13.427,35.675) 13.452,35.699 13.539,35.699 13.563,35.722 16.758,35.722 19.806,35.722 19.904,35.625 D31.1@21.016,35.625 21.254,35.625 21.351,35.722 21.662,35.722 22.179,35.205 22.357,35.027 22.846,35.027 22.859,35.014 23.637,35.014 J10.41@23.726,34.925 ; MODULE1.BF16@75.882,99.436 76.03,99.88 v2(76.082,100.036)
  L3 w0.117: v1(13.427,35.675) 13.453,35.7 13.54,35.7 13.562,35.722 13.854,35.722 14.161,36.029 14.161,39.264 12.806,40.618 12.806,55.416 18.599,61.209 52.657,61.209 52.835,61.388 57.531,66.083 57.531,88.344 68.54,99.353 75.787,99.353 76.034,99.6 76.034,99.901 76.057,99.923 76.057,100.011 v2(76.082,100.036)
  other v1: 76.082,100.036
  other v2: 13.427,35.675
MD_PCIE1_4LANES.RX0_1_P: D31.2 D31.9 J10.43 MODULE1.BF17 | length 127.2
  TOP_L1 w0.122: v1(13.427,36.075) 13.452,36.05 13.539,36.05 13.563,36.027 16.632,36.027 19.806,36.027 19.904,36.125 D31.2@21.016,36.125 21.254,36.125 21.351,36.027 21.788,36.027 22.484,35.331 22.854,35.331 22.859,35.336 23.637,35.336 J10.43@23.726,35.425 ; v2(75.682,100.036) 75.734,100.192 MODULE1.BF17@75.882,100.636
  L3 w0.117: v1(13.427,36.075) 13.453,36.049 13.54,36.049 13.562,36.027 13.727,36.027 13.856,36.156 13.856,39.137 12.501,40.492 12.501,55.543 18.472,61.514 18.519,61.514 51.618,61.514 51.676,61.514 51.745,61.582 51.745,61.779 51.79,61.824 52,61.824 52.046,61.779 52.046,61.582 52.114,61.514 52.53,61.514 53.087,62.071 57.226,66.21 57.226,88.471 68.413,99.658 75.661,99.658 75.73,99.726 75.73,99.901 75.708,99.923 75.708,100.011 v2(75.682,100.036)
  other v1: 75.682,100.036
  other v2: 13.427,36.075
MD_PCIE1_4LANES.RX1_1_N: D30.1 D30.10 J10.29 MODULE1.BE15 | length 126.8
  TOP_L1 w0.122: v1@13.873,32.833 13.963,32.922 19.806,32.922 19.904,32.825 D30.1@21.016,32.825 21.254,32.825 21.351,32.922 21.593,32.922 21.85,32.665 22.051,32.464 22.051,32.277 22.301,32.027 22.846,32.027 22.859,32.014 23.637,32.014 J10.29@23.726,31.925 ; MODULE1.BE15@74.682,98.236 74.83,98.68 v2(74.882,98.836)
  L3 w0.117: v2(13.827,32.875) 13.853,32.9 13.94,32.9 13.962,32.922 14.47,32.922 15.411,33.863 15.411,39.585 15.411,39.83 14.306,40.934 14.306,54.651 18.614,58.959 53.101,58.959 53.279,59.138 58.919,64.778 58.919,87.605 69.467,98.153 74.587,98.153 74.834,98.4 74.834,98.701 74.857,98.723 74.857,98.811 v2(74.882,98.836)
  other v1: 13.827,32.875 74.882,98.836
MD_PCIE1_4LANES.RX1_1_P: D30.2 D30.9 J10.31 MODULE1.BE16 | length 126.8
  TOP_L1 w0.122: v1@13.939,33.25 13.962,33.227 19.806,33.227 19.904,33.325 21.254,33.325 21.351,33.227 21.719,33.227 22.356,32.59 22.356,32.403 22.427,32.331 22.854,32.331 22.859,32.336 23.637,32.336 J10.31@23.726,32.425 ; v2(74.482,98.836) 74.534,98.992 MODULE1.BE16@74.682,99.436
  L3 w0.117: v1(13.827,33.275) 13.853,33.249 13.94,33.249 13.962,33.227 14.343,33.227 15.106,33.99 15.106,39.703 14.001,40.808 14.001,54.778 18.487,59.264 51.62,59.264 51.679,59.264 51.747,59.332 51.747,59.553 51.807,59.613 51.988,59.613 52.048,59.553 52.048,59.332 52.116,59.264 52.974,59.264 53.014,59.303 53.072,59.361 58.614,64.904 58.614,87.731 69.341,98.458 74.461,98.458 74.53,98.526 74.53,98.701 74.508,98.723 74.508,98.811 v2(74.482,98.836)
  other v1: 74.482,98.836
  other v2: 13.827,33.275
MD_PCIE1_4LANES.RX2_1_N: D29.1 D29.10 J10.17 MODULE1.BD14 | length 124.1
  TOP_L1 w0.122: v1@15.137,30.937 15.16,30.96 16.781,30.96 17.619,30.122 19.806,30.122 19.904,30.025 D29.10@20.141,30.025 D29.1@21.016,30.025 21.254,30.025 21.351,30.122 21.502,30.122 21.945,29.679 22.597,29.027 22.846,29.027 22.859,29.014 23.637,29.014 J10.17@23.726,28.925 ; MODULE1.BD14@73.482,97.036 73.63,97.48 v2(73.682,97.636)
  L3 w0.117: v1(15.025,30.913) 15.05,30.938 15.138,30.938 15.16,30.96 15.627,30.96 16.661,31.994 16.661,40.335 16.661,40.88 15.806,41.734 15.806,53.774 18.741,56.709 53.228,56.709 53.406,56.888 60.403,63.884 60.403,86.861 70.495,96.953 73.387,96.953 73.634,97.2 73.634,97.501 73.657,97.523 73.657,97.611 v2(73.682,97.636)
  other v1: 73.682,97.636
  other v2: 15.025,30.913
MD_PCIE1_4LANES.RX2_1_P: D29.2 D29.9 J10.19 MODULE1.BD15 | length 124.1
  TOP_L1 w0.122: v1(15.025,31.313) 15.049,31.288 15.137,31.288 15.16,31.265 16.907,31.265 17.745,30.427 19.806,30.427 19.904,30.525 D29.9@20.141,30.525 D29.2@21.016,30.525 21.254,30.525 21.351,30.427 21.628,30.427 22.25,29.805 22.724,29.331 22.854,29.331 22.859,29.336 23.637,29.336 J10.19@23.726,29.425 ; v2(73.282,97.636) 73.334,97.792 MODULE1.BD15@73.482,98.236
  L3 w0.117: v1(15.025,31.313) 15.05,31.287 15.138,31.287 15.16,31.265 15.5,31.265 16.356,32.121 16.356,40.753 15.501,41.608 15.501,53.201 15.501,53.901 18.614,57.014 51.568,57.014 51.627,57.014 51.695,57.082 51.695,57.217 51.755,57.277 51.936,57.277 51.996,57.217 51.996,57.082 52.065,57.014 52.827,57.014 53.101,57.014 60.098,64.01 60.098,86.987 70.369,97.258 73.261,97.258 73.33,97.326 73.33,97.501 73.308,97.523 73.308,97.611 v2(73.282,97.636)
  other v1: 73.282,97.636
  other v2: 15.025,31.313
MD_PCIE1_4LANES.RX3_1_N: D28.1 D28.10 J10.5 MODULE1.BC13 | length 123.1
  TOP_L1 w0.122: v2(15.443,29.502) 15.467,29.526 15.555,29.526 15.578,29.549 16.334,29.549 17.39,28.493 18.564,27.32 19.618,27.32 19.621,27.322 19.806,27.322 19.904,27.225 D28.10@20.141,27.225 D28.1@21.016,27.225 21.254,27.225 21.351,27.322 21.693,27.322 21.945,27.07 21.945,26.439 22.357,26.027 22.846,26.027 22.859,26.014 23.637,26.014 J10.5@23.726,25.925 ; MODULE1.BC13@72.282,95.836 72.43,96.28 v2(72.482,96.436)
  L3 w0.117: v2(15.443,29.502) 15.468,29.527 15.555,29.527 15.578,29.549 16.087,29.549 16.265,29.728 17.176,30.639 17.822,31.284 17.911,31.373 17.911,41.085 17.911,41.73 17.306,42.334 17.306,52.909 18.801,54.404 53.559,54.404 53.738,54.583 61.748,62.593 61.927,62.772 61.927,86.252 71.427,95.753 72.187,95.753 72.434,96 72.434,96.301 72.457,96.323 72.457,96.411 v2(72.482,96.436)
  other v1: 15.443,29.502 72.482,96.436
MD_PCIE1_4LANES.RX3_1_P: D28.2 D28.9 J10.7 MODULE1.BC14 | length 123.1
  TOP_L1 w0.122: v1(15.443,29.902) 15.467,29.877 15.555,29.877 15.578,29.854 16.461,29.854 18.69,27.625 19.492,27.625 19.494,27.627 19.806,27.627 19.904,27.725 D28.9@20.141,27.725 D28.2@21.016,27.725 21.254,27.725 21.351,27.627 21.819,27.627 22.25,27.196 22.25,26.565 22.484,26.331 22.854,26.331 22.859,26.336 23.637,26.336 J10.7@23.726,26.425 ; v2(72.082,96.436) 72.134,96.592 MODULE1.BC14@72.282,97.036
  L3 w0.117: v1(15.443,29.902) 15.468,29.876 15.555,29.876 15.578,29.854 15.961,29.854 17.606,31.5 17.606,41.603 17.001,42.208 17.001,52.335 17.001,53.035 18.675,54.709 51.568,54.709 51.626,54.709 51.695,54.777 51.695,54.983 51.755,55.043 51.936,55.043 51.996,54.983 51.996,54.777 52.064,54.709 53.378,54.709 53.433,54.709 61.622,62.898 61.622,86.379 71.301,96.058 72.061,96.058 72.13,96.126 72.13,96.301 72.108,96.323 72.108,96.411 v2(72.082,96.436)
  other v1: 72.082,96.436
  other v2: 15.443,29.902
MD_PCIE1_4LANES.TX0_1_N: D31.4 D31.7 J10.47 MODULE1.BF12 | length 117.8
  TOP_L1 w0.122: v1(19.406,37.075) 19.553,37.222 19.806,37.222 19.904,37.125 D31.7@20.141,37.125 D31.4@21.016,37.125 21.254,37.125 21.351,37.222 21.593,37.222 21.95,36.865 22.034,36.781 22.034,36.777 22.284,36.527 22.846,36.527 22.859,36.514 23.637,36.514 J10.47@23.726,36.425 ; MODULE1.BF12@75.882,94.636 76.091,95.055 v1(76.182,95.236)
  L8 w0.117: v1(19.406,37.075) 19.468,37.075 19.616,37.222 20.146,37.222 20.393,37.469 20.393,38.672 20.215,38.85 12.145,46.92 12.145,54.718 18.637,61.209 47.544,61.209 50.803,61.209 50.982,61.388 56.537,66.943 56.715,67.122 56.715,83.313 67.841,94.439 75.739,94.439 76.034,94.735 76.034,95.026 76.182,95.174 v1(76.182,95.236)
  other v2: 19.406,37.075 19.406,37.075 76.182,95.236
  other v5: 19.406,37.075 76.182,95.236
MD_PCIE1_4LANES.TX0_1_P: D31.5 D31.6 J10.49 MODULE1.BF13 | length 117.9
  TOP_L1 w0.122: v1(19.406,37.675) 19.553,37.527 19.806,37.527 19.904,37.625 D31.6@20.141,37.625 D31.5@21.016,37.625 21.254,37.625 21.351,37.527 21.719,37.527 22.338,36.908 22.338,36.903 22.41,36.831 22.854,36.831 22.859,36.836 23.637,36.836 J10.49@23.726,36.925 ; v1(75.582,95.236) 75.673,95.418 MODULE1.BF13@75.882,95.836
  L8 w0.117: v1(19.406,37.675) 19.468,37.675 19.616,37.527 20.02,37.527 20.088,37.596 20.088,38.546 11.84,46.794 11.84,54.844 18.51,61.514 48.846,61.514 48.904,61.514 49.015,61.625 49.015,61.832 49.126,61.943 49.459,61.943 49.57,61.832 49.57,61.625 49.681,61.514 50.677,61.514 51.213,62.05 51.272,62.109 56.411,67.248 56.411,83.439 67.715,94.744 75.613,94.744 75.73,94.861 75.73,95.026 75.582,95.174 v1(75.582,95.236)
  other v2: 19.406,37.675 75.582,95.236
  other v5: 19.406,37.675 75.582,95.236
MD_PCIE1_4LANES.TX1_1_N: D30.4 D30.7 J10.35 MODULE1.BE11 | length 118.2
  TOP_L1 w0.122: v1(19.406,34.275) 19.553,34.422 19.806,34.422 D30.7@19.904,34.325 ; D30.7@20.141,34.325 21.254,34.325 21.351,34.422 21.693,34.422 21.95,34.165 22.05,34.065 22.05,33.777 22.3,33.527 22.846,33.527 22.859,33.514 23.637,33.514 J10.35@23.726,33.425 ; MODULE1.BE11@74.682,93.436 74.891,93.855 v1(74.982,94.036)
  L8 w0.117: v1(19.406,34.275) 19.468,34.275 19.616,34.422 20.974,34.422 21.153,34.601 21.685,35.133 21.863,35.311 21.863,39.202 21.685,39.38 13.606,47.459 13.606,53.778 18.787,58.959 41.365,58.959 50.545,58.959 51.541,58.959 51.72,59.138 58.218,65.636 58.396,65.814 58.396,82.402 69.234,93.239 74.539,93.239 74.834,93.535 74.834,93.826 74.982,93.974 v1(74.982,94.036)
  other v2: 19.406,34.275 19.406,34.275 74.982,94.036
  other v5: 19.406,34.275 74.982,94.036
MD_PCIE1_4LANES.TX1_1_P: D30.5 D30.6 J10.37 MODULE1.BE12 | length 118.3
  TOP_L1 w0.122: v1(19.406,34.875) 19.553,34.727 19.806,34.727 D30.6@19.904,34.825 ; D30.6@20.141,34.825 21.254,34.825 21.351,34.727 21.819,34.727 22.355,34.191 22.355,33.903 22.426,33.831 22.854,33.831 22.859,33.836 23.637,33.836 J10.37@23.726,33.925 ; v1(74.382,94.036) 74.473,94.218 MODULE1.BE12@74.682,94.636
  L8 w0.117: v1(19.406,34.875) 19.468,34.875 19.616,34.727 20.848,34.727 21.559,35.438 21.559,39.075 13.301,47.333 13.301,53.905 18.66,59.264 48.837,59.264 48.896,59.264 49.007,59.375 49.007,59.566 49.118,59.677 49.451,59.677 49.562,59.566 49.562,59.375 49.673,59.264 49.9,59.264 51.415,59.264 58.092,65.94 58.092,82.528 69.108,93.544 74.413,93.544 74.53,93.661 74.53,93.826 74.382,93.974 v1(74.382,94.036)
  other v2: 19.406,34.875 74.382,94.036
  other v5: 19.406,34.875 74.382,94.036
MD_PCIE1_4LANES.TX2_1_N: D29.4 D29.7 J10.23 MODULE1.BD10 | length 118.3
  TOP_L1 w0.122: v1(19.406,31.475) 19.553,31.622 19.806,31.622 D29.7@19.904,31.525 ; D29.7@20.141,31.525 D29.4@21.016,31.525 21.254,31.525 21.351,31.622 21.508,31.622 22.039,31.091 22.425,30.705 22.603,30.527 22.846,30.527 22.859,30.514 23.637,30.514 J10.23@23.726,30.425 ; MODULE1.BD10@73.482,92.236 73.691,92.655 v1(73.782,92.836)
  L8 w0.117: v1(19.406,31.475) 19.468,31.475 19.616,31.622 21.396,31.622 23.402,33.629 23.402,40.163 23.224,40.341 15.106,48.459 15.106,52.878 18.937,56.709 51.876,56.709 52.055,56.888 59.764,64.597 59.943,64.775 59.943,81.68 70.302,92.039 73.339,92.039 73.634,92.335 73.634,92.626 73.782,92.774 v1(73.782,92.836)
  other v2: 19.406,31.475 73.782,92.836
  other v5: 19.406,31.475 73.782,92.836
MD_PCIE1_4LANES.TX2_1_P: D29.5 D29.6 J10.25 MODULE1.BD11 | length 118.4
  TOP_L1 w0.122: v1(19.406,32.075) 19.553,31.927 19.806,31.927 D29.6@19.904,32.025 ; D29.6@20.141,32.025 D29.5@21.016,32.025 21.254,32.025 21.351,31.927 21.634,31.927 22.166,31.395 22.73,30.831 22.854,30.831 22.859,30.836 23.637,30.836 J10.25@23.726,30.925 ; v1(73.182,92.836) 73.273,93.018 MODULE1.BD11@73.482,93.436
  L8 w0.117: v1(19.406,32.075) 19.468,32.075 19.616,31.927 21.27,31.927 23.097,33.755 23.097,40.037 14.801,48.333 14.801,53.005 18.81,57.014 48.759,57.014 48.818,57.014 48.929,57.125 48.929,57.328 49.04,57.439 49.372,57.439 49.483,57.328 49.483,57.125 49.594,57.014 50.763,57.014 50.821,57.014 51.75,57.014 59.638,64.902 59.638,81.806 70.176,92.344 73.213,92.344 73.33,92.461 73.33,92.626 73.182,92.774 v1(73.182,92.836)
  other v2: 19.406,32.075 73.182,92.836
  other v5: 19.406,32.075 73.182,92.836
MD_PCIE1_4LANES.TX3_1_N: D28.4 D28.7 J10.11 MODULE1.BC9 | length 118.2
  TOP_L1 w0.122: v2(19.406,28.675) 19.553,28.822 19.806,28.822 D28.7@19.904,28.725 ; D28.7@20.141,28.725 D28.4@21.016,28.725 21.254,28.725 21.351,28.822 21.565,28.822 22.039,28.349 22.039,28.187 22.697,27.529 22.91,27.529 22.926,27.514 23.637,27.514 J10.11@23.726,27.425 ; MODULE1.BC9@72.282,91.036 72.491,91.455 v5(72.582,91.636)
  L8 w0.117: v2(19.406,28.675) 19.468,28.675 19.616,28.822 21.211,28.822 24.854,32.465 24.854,41.211 16.606,49.459 16.606,52.209 18.856,54.459 52.017,54.459 52.196,54.638 61.179,63.621 61.357,63.799 61.357,80.711 71.267,90.62 71.92,90.62 72.434,91.135 72.434,91.426 72.582,91.574 v5(72.582,91.636)
  other v1: 19.406,28.675 72.582,91.636
  other v2: 72.582,91.636
  other v5: 19.406,28.675
MD_PCIE1_4LANES.TX3_1_P: D28.5 D28.6 J10.13 MODULE1.BC10 | length 118.1
  TOP_L1 w0.122: v5(19.406,29.275) 19.553,29.127 19.806,29.127 D28.6@19.904,29.225 ; D28.6@20.141,29.225 D28.5@21.016,29.225 21.254,29.225 21.351,29.127 21.691,29.127 22.343,28.475 22.343,28.314 22.823,27.834 22.924,27.834 22.926,27.836 23.637,27.836 J10.13@23.726,27.925 ; v1(71.982,91.636) 72.073,91.818 MODULE1.BC10@72.282,92.236
  L8 w0.117: v5(19.406,29.275) 19.468,29.275 19.616,29.127 21.084,29.127 24.549,32.591 24.549,41.085 16.301,49.333 16.301,52.335 18.73,54.764 48.767,54.764 48.825,54.764 48.909,54.847 48.909,54.992 48.992,55.075 49.38,55.075 49.464,54.992 49.464,54.847 49.547,54.764 51.274,54.764 51.891,54.764 61.053,63.926 61.053,80.837 71.141,90.925 71.794,90.925 72.13,91.261 72.13,91.426 71.982,91.574 v1(71.982,91.636)
  other v1: 19.406,29.275
  other v2: 19.406,29.275 71.982,91.636
  other v5: 71.982,91.636
MD_QUP1_SE4_I2C_3V3.SCL_1: R155.2 R311.2 R318.1 U20.5 U33_1.20 | length 334.2
  TOP_L1 w0.127: v1(14.126,133.168) 14.159,133.168 14.245,133.253 15.161,133.253 15.901,132.513 15.901,130.524 16.351,130.074 U20.5@17.174,130.074 ; R311.2@47.961,36.549 49.432,36.549 49.581,36.698 49.581,37.761 53.9,42.08 59.893,42.08 65.481,47.669 65.481,51.749 64.328,52.902 v1(64.328,53.475)
  L2 w0.127: v3(63.566,55.186) 63.562,55.183 63.562,54.241 v1(64.328,53.475)
  L3 w0.127: v1(14.126,133.168) 14.126,136.226 15.3,137.4 15.3,143.781 14.494,144.587 11.06,144.587 9.435,146.212 9.435,156.896 11.724,159.186 55.786,159.186 56.354,158.617 76.356,158.617 77.293,157.68 83.711,157.68 85.091,156.3 85.091,150.553 v5(85.11,150.534)
  L8 w0.127: v3(76.864,30.742) 77.277,31.155 77.277,31.448 77.438,31.61 77.438,31.643 77.651,31.856 77.952,31.856 77.971,31.838 79.128,31.838 79.276,31.986 79.276,46.665 78.96,46.981 v3(78.96,48.066) 78.96,48.925 78.707,49.178 78.707,49.785 77.482,51.01 77.482,65.635 76.099,67.018 76.099,77.152 84.195,85.247 84.195,99.852 83.412,100.635 83.412,101.19 83.307,101.295 83.307,102.726 82.562,103.471 82.562,105.363 80.09,107.835 70.958,107.835 68.817,109.976 68.817,115.91 71.242,118.335 73.975,118.335 75.952,120.312 85.98,120.312 87.678,122.01 87.678,125.234 87.288,125.625 v3(86.662,125.625) 85.875,125.625 85.709,125.791 85.709,126.899 85.88,127.07 90.159,127.07 92.472,129.384 92.472,143.172 v5(85.11,150.534)
  BOTTOM_L10 w0.127: v3(63.566,55.186) 63.566,54.226 66.325,51.467 74.738,51.467 75.727,50.478 75.727,48.381 76.206,47.902 78.796,47.902 v3(78.96,48.066) ; v3(76.864,30.742) 76.865,30.74 76.865,30.375 R318.1@76.866,30.374 ; U33_1.20@85.725,125.55 86.32,125.55 86.395,125.625 v3(86.662,125.625) R155.2@87.025,125.625
  other v2: 63.566,55.186 14.126,133.168
  other v4: 76.864,30.742 78.96,48.066 63.566,55.186 86.662,125.625
  other v5: 63.57,55.19
MD_QUP1_SE4_I2C_3V3.SDA_1: R158.2 R189.1 R310.2 U20.6 U33_1.18 | length 332.7
  TOP_L1 w0.127: v2(14.47,133.551) 15.47,133.551 16.285,132.736 16.285,130.988 16.549,130.724 U20.6@17.174,130.724 ; R310.2@47.961,37.899 47.961,38.51 49.671,40.22 51.719,40.22 53.806,42.307 59.799,42.307 65.254,47.763 65.254,51.655 64.005,52.904 v1(64.005,53.335) ; R189.1@80.667,29.85 v1(81.066,29.85)
  L2 w0.127: v5(80.417,29.845) 80.42,29.848 81.031,29.848 v2@81.034,29.851
  L3 w0.127: v2(14.47,133.551) 14.47,135.47 15.7,136.7 15.7,144.1 14.88,144.92 11.048,144.92 9.673,146.295 9.673,156.592 12.04,158.959 55.692,158.959 56.26,158.39 76.262,158.39 77.199,157.453 83.572,157.453 84.653,156.372 v5(84.653,151.611) ; v5(63.087,54.841) 63.087,54.252 v1(64.005,53.335) ; v5(80.417,29.845) 80.422,29.85 v1(81.066,29.85)
  L8 w0.127: v5(80.417,29.845) 80.061,30.2 80.061,30.506 79.436,31.131 79.436,31.581 79.503,31.648 79.503,46.762 79.382,46.883 v3(79.382,47.562) 79.375,47.569 79.375,49.056 78.934,49.496 78.934,49.958 77.765,51.127 77.765,65.752 76.382,67.135 76.382,77.035 84.421,85.074 84.421,100.228 83.639,101.011 83.639,101.284 83.534,101.389 83.534,102.821 82.789,103.565 82.789,105.457 80.184,108.062 71.155,108.062 69.746,109.471 69.746,116.518 71.263,118.035 74.775,118.035 76.79,120.05 86.039,120.05 87.965,121.975 87.965,124.325 90.394,126.754 ; v5(84.653,151.611) 92.699,143.564 92.699,129.059 90.394,126.754 ; v4(86.726,126.754) 90.394,126.754
  BOTTOM_L10 w0.127: v5(63.087,54.841) 63.087,54.246 66.093,51.24 74.644,51.24 75.5,50.384 75.5,48.059 76.006,47.553 79.374,47.553 v3(79.382,47.562) ; U33_1.18@84.825,126.45 84.825,126.852 85.146,127.173 86.077,127.173 86.496,126.754 v4(86.726,126.754) R158.2@86.725,127.275 R158.2@86.725,127.275
  other v1: 14.47,133.551
  other v2: 80.417,29.845 81.066,29.85 64.005,53.335
  other v3: 63.087,54.841 86.726,126.754
  other v4: 79.382,47.562 63.087,54.841
MD_SGMII0.RX_1_N: C112.2 MODULE1.BF26 | length 167.5
  TOP_L1 w0.109: v2(63.65,7.1) 63.688,7.1 63.791,7.203 64.138,7.203 C112.2@64.341,7 ; MODULE1.BF26@75.882,111.436 75.938,111.436 76.239,111.136 76.444,111.136 77.242,110.337 77.984,110.337 v5(78.182,110.535)
  L3 w0.104: v2(63.65,7.1) v5(63.942,7.1)
  L8 w0.104: v5(63.942,7.1) 63.999,7.156 64.171,7.156 64.212,7.197 64.803,7.197 64.982,7.376 65.499,7.893 65.678,8.072 65.678,10.005 67.346,11.674 75.877,11.674 78.653,8.899 78.832,8.72 82.727,8.72 85.037,11.03 85.037,15.015 86.954,16.931 90.408,16.931 91.517,18.04 91.606,18.129 91.606,28.75 95.856,33 95.856,49.88 95.856,50.148 95.224,50.779 93.061,50.779 92.608,51.232 92.608,52.138 93.061,52.591 95.224,52.591 95.856,53.223 95.856,54.103 95.856,63.059 94.157,64.758 93.31,65.605 89.311,65.605 87.485,67.43 87.385,67.53 87.296,67.62 86.87,67.62 85.556,66.306 85.383,66.306 85.124,66.566 85.124,66.739 86.48,68.095 86.48,68.521 86.042,68.959 85.616,68.959 84.996,68.339 84.823,68.339 84.564,68.599 84.564,68.772 85.141,69.349 85.141,69.775 84.712,70.204 84.612,70.304 84.471,70.445 84.471,78.57 87.227,81.327 87.835,81.935 87.925,82.024 87.925,82.417 87.925,84.239 88.055,84.239 88.055,84.851 87.925,84.851 87.925,84.904 87.925,87.515 88.732,88.322 90.137,88.322 90.315,88.5 91.064,89.25 91.433,89.618 91.522,89.707 91.522,102.784 84.369,109.937 83.969,110.337 78.391,110.337 78.193,110.535 v5(78.182,110.535)
  other v1: 63.65,7.1 78.182,110.535
  other v2: 78.182,110.535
